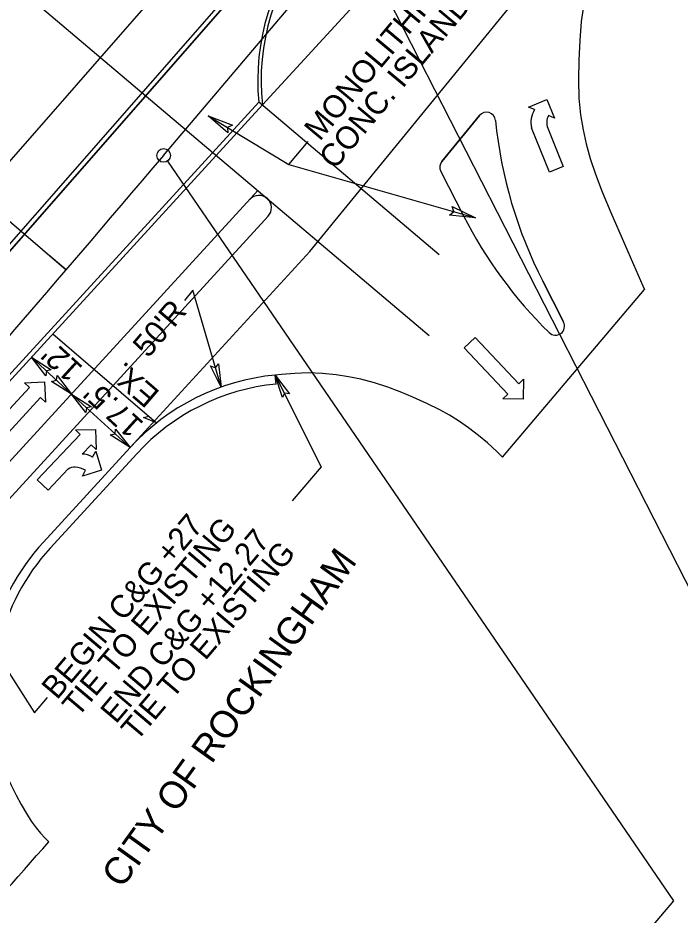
# Model space of a CAD drawing. Extents: x 1761082 to 1764358, y 421907 to 425434.
# Drawn here: x 1763028.7 to 1763174.6, y 423828.1 to 424026 of the extents above; entities that cross this region are included whole.
import ezdxf

# ---------------------------------------------------------------- set-up
doc = ezdxf.new("R2010")
doc.units = 0
for name, color, linetype in [('MARK DUAL LEFT TURN ARROWS CELL', 7, 'Continuous'), ('MARK HOOKS CENTER STRAIGHT LEFT TURN ARROW CELL', 7, 'Continuous'), ('MARK LEFT TURN ARROW CELL', 7, 'Continuous'), ('MARK STRAIGHT RIGHT ARROW CELL', 7, 'Continuous'), ('MARK UTURN ARROW CELL', 7, 'Continuous'), ('Prop Mkg 3ft Min Skp 3ft Wide White', 7, 'Continuous'), ('Prop Mkg Min Skp 6ft Yellow', 7, 'Continuous'), ('Prop Mkg Skp Wht', 7, 'Continuous'), ('Prop Mkg Solid White Diagonals', 7, 'Continuous'), ('Prop Mkg Solid White Lane Line', 7, 'Continuous'), ('Prop Mkg Solid White Multiple Diagonals V8i', 7, 'Continuous'), ('Prop Mkg Solid Yel Skip LT', 7, 'Continuous'), ('Prop Mkg Solid Yel Skip RT', 7, 'Continuous'), ('Prop Mkg Solid Yellow Diagonals', 7, 'Continuous'), ('Prop Mkg Solid Yellow Edge Line', 7, 'Continuous'), ('Prop Mkg Solid Yellow Lane Line', 7, 'Continuous'), ('Scratch_Level_0', 7, 'Continuous'), ('Scratch_Level_5', 7, 'Continuous')]:
    doc.layers.add(name, color=color, linetype=linetype)

msp = doc.modelspace()

# ---------------------------------------------------------------- linework, layer by layer
at = {"layer": 'MARK DUAL LEFT TURN ARROWS CELL'}
msp.add_line((1762975.13, 424025.41), (1763039.28, 423970.45), dxfattribs=at)
at = {"layer": 'MARK HOOKS CENTER STRAIGHT LEFT TURN ARROW CELL'}
msp.add_line((1763039.28, 423970.45), (1763035.48, 423973.71), dxfattribs=at)
at = {"layer": 'MARK LEFT TURN ARROW CELL'}
for p, q in [((1763085.59, 423945.25), (1763085.39, 423947.25)), ((1763035.74, 423909.03), (1763054.85, 423929.9))]:
    msp.add_line(p, q, dxfattribs=at)
for centre, start, end in [((1763090.25, 423897.48), 95.5758, 137.5234), ((1763071.14, 423876.61), 137.5234, 166.7543)]:
    msp.add_arc(centre, 48, start, end, dxfattribs=at)
at = {"layer": 'MARK STRAIGHT RIGHT ARROW CELL'}
msp.add_line((1763060.78, 423995.7), (1763460.21, 424467.19), dxfattribs=at)
msp.add_arc((1758482.74, 427874.03), 6000, 317.523415, 319.730103, dxfattribs=at)
at = {"layer": 'MARK UTURN ARROW CELL'}
msp.add_lwpolyline([(1763061.63, 423994.46), (1763173.2, 423831.29), (1763102.23, 423747.51)], dxfattribs=at)
msp.add_circle((1763060.78, 423995.7), 1.5, dxfattribs=at)
at = {"layer": 'Prop Mkg 3ft Min Skp 3ft Wide White'}
msp.add_line((1763060.78, 423995.7), (1763460.21, 424467.19), dxfattribs=at)
msp.add_arc((1758482.74, 427874.03), 6000, 317.523415, 319.730103, dxfattribs=at)
at = {"layer": 'Prop Mkg Skp Wht'}
for p, q in [((1763135.48, 423929.16), (1763166.78, 423966.11)), ((1763034.27, 423910.38), (1763053.37, 423931.25))]:
    msp.add_line(p, q, dxfattribs=at)
for points in [[(1763153.38, 424029.09), (1763152.86, 424025.26), (1763152.54, 424021.03), (1763152.32, 424016.7), (1763152.21, 424012.38), (1763152.34, 424008.35), (1763152.71, 424004.67), (1763153.24, 424001.33), (1763153.92, 423998.27), (1763154.83, 423995.03), (1763155.99, 423991.53), (1763157.46, 423987.67), (1763159.37, 423983.14), (1763162.39, 423976.16), (1763164.36, 423971.64), (1763166.43, 423966.9), (1763166.78, 423966.11)], [(1763135.48, 423929.16), (1763134.24, 423930.4), (1763132.21, 423932.26), (1763130.17, 423933.94), (1763127.97, 423935.61), (1763125.8, 423937.13), (1763123.83, 423938.39), (1763121.64, 423939.6), (1763118.78, 423940.99), (1763115.72, 423942.37), (1763112.95, 423943.56), (1763110.2, 423944.6), (1763107.23, 423945.54), (1763104.27, 423946.31), (1763101.54, 423946.87), (1763098.79, 423947.27), (1763095.77, 423947.56), (1763092.66, 423947.7), (1763089.68, 423947.61), (1763086.78, 423947.38), (1763085.39, 423947.25)], [(1763022.48, 423888.07), (1763022.37, 423887.64), (1763022.01, 423885.7), (1763021.78, 423883.92), (1763021.64, 423882.16), (1763021.52, 423880.28), (1763021.46, 423878.23), (1763021.51, 423875.93), (1763021.77, 423873.37), (1763022.32, 423870.5), (1763022.98, 423867.75), (1763023.58, 423865.5), (1763024.23, 423863.47), (1763025.04, 423861.39), (1763026, 423859.2), (1763027.08, 423856.89), (1763028.24, 423854.59), (1763029.39, 423852.48), (1763030.53, 423850.55), (1763031.6, 423848.83), (1763032.64, 423847.34), (1763033.63, 423846.15), (1763034.61, 423845.13), (1763035.49, 423844.29)]]:
    msp.add_lwpolyline(points, dxfattribs=at)
for centre, radius, start, end in [((1763090.25, 423897.48), 50, 95.5758, 137.5234), ((1763071.14, 423876.61), 50, 137.5234, 166.7543), ((1758482.74, 427874.03), 6080, 318.179172, 318.487231)]:
    msp.add_arc(centre, radius, start, end, dxfattribs=at)
at = {"layer": 'Prop Mkg Solid White Diagonals'}
for p, q in [((1763090.51, 424047.41), (1762859.56, 423783.42)), ((1762783.48, 423681.64), (1763081.76, 424007.42)), ((1763130.4, 424004.48), (1763122.12, 423994.36)), ((1763121.88, 423992.18), (1763126.88, 423982.39)), ((1763148.94, 423958.95), (1763144.36, 423967.93))]:
    msp.add_line(p, q, dxfattribs=at)
for centre, radius, start, end in [((1763131.52, 424012.29), 50, 139.7301, 185.5882), ((1763131.94, 424003.22), 2, 5.7105, 140.7423), ((1763233.44, 424013.37), 100, 185.7105, 207.0244), ((1763123.67, 423993.09), 2, 140.7423, 207.0244), ((1763215.96, 424027.83), 100, 207.0244, 225.4056), ((1763147.16, 423958.04), 2, 225.4056, 27.0244)]:
    msp.add_arc(centre, radius, start, end, dxfattribs=at)
at = {"layer": 'Prop Mkg Solid White Lane Line'}
for p, q in [((1762859.56, 423783.42), (1763090.51, 424047.41)), ((1762783.48, 423681.64), (1763081.76, 424007.42)), ((1763122.12, 423994.36), (1763130.4, 424004.48)), ((1763121.88, 423992.18), (1763126.88, 423982.39)), ((1763144.36, 423967.93), (1763148.94, 423958.95))]:
    msp.add_line(p, q, dxfattribs=at)
for centre, radius, start, end in [((1763131.52, 424012.29), 50, 139.7301, 185.5882), ((1763131.94, 424003.22), 2, 5.7105, 140.7423), ((1763233.44, 424013.37), 100, 185.7105, 207.0244), ((1763123.67, 423993.09), 2, 140.7423, 207.0244), ((1763215.96, 424027.83), 100, 207.0244, 225.4056), ((1763147.16, 423958.04), 2, 225.4056, 27.0244)]:
    msp.add_arc(centre, radius, start, end, dxfattribs=at)
at = {"layer": 'Prop Mkg Solid White Multiple Diagonals V8i'}
for p, q in [((1763006.96, 424051.12), (1763119.33, 423955.94)), ((1763102.71, 424045.18), (1763292.23, 423673.61)), ((1763121.49, 423973.76), (1763081.76, 424007.42)), ((1762988.96, 423878.66), (1763083.82, 423982.27))]:
    msp.add_line(p, q, dxfattribs=at)
msp.add_arc((1763081.79, 423984.13), 2.75, 317.5234, 137.5234, dxfattribs=at)
at = {"layer": 'Prop Mkg Solid Yel Skip RT'}
for p, q in [((1763088.35, 423993.73), (1763129.54, 423981.93)), ((1763040.47, 423943.06), (1763031.61, 423951.17)), ((1763053.37, 423931.25), (1763040.47, 423943.06))]:
    msp.add_line(p, q, dxfattribs=at)
for points in [[(1763070.57, 424004.41), (1763088.35, 423993.73), (1763092.61, 423998.75)], [(1763073.44, 423944.57), (1763067.25, 423965.96), (1763065.36, 423963.72)], [(1763085.39, 423947.25), (1763095.5, 423927.03), (1763089.11, 423919.49)], [(1763022.48, 423888.07), (1763032.31, 423872.76), (1763035.15, 423876.11)]]:
    msp.add_lwpolyline(points, dxfattribs=at)
at = {"layer": 'Prop Mkg Solid Yellow Diagonals'}
for p, q in [((1763141.2, 424006.38), (1763145.26, 424008.06)), ((1763145.26, 424008.06), (1763146.98, 424003.9)), ((1763142.56, 424005.8), (1763141.2, 424006.38)), ((1763146.98, 424003.9), (1763145.62, 424004.49)), ((1763145.81, 423992.02), (1763141.89, 424001.81)), ((1763145.48, 424001.74), (1763148.88, 423993.25)), ((1763148.88, 423993.25), (1763145.81, 423992.02)), ((1763127.07, 423953.26), (1763129.48, 423955.52)), ((1763129.48, 423955.52), (1763139.05, 423945.3)), ((1763136.64, 423943.04), (1763127.07, 423953.26)), ((1763030.07, 423945.53), (1763034.48, 423945.75)), ((1763031.17, 423944.51), (1763030.07, 423945.53)), ((1763034.48, 423945.75), (1763034.71, 423941.26)), ((1763139.05, 423945.3), (1763140.14, 423946.32)), ((1763140.14, 423946.32), (1763140.03, 423941.9)), ((1763021.7, 423934.21), (1763031.17, 423944.51)), ((1763033.6, 423942.28), (1763024.13, 423931.98)), ((1763034.71, 423941.26), (1763033.6, 423942.28)), ((1763135.54, 423942.02), (1763136.64, 423943.04)), ((1763140.03, 423941.9), (1763135.54, 423942.02)), ((1763032.91, 423924.11), (1763042.4, 423934.14)), ((1763041.31, 423935.17), (1763045.73, 423935.25)), ((1763042.4, 423934.14), (1763041.31, 423935.17)), ((1763045.73, 423935.25), (1763045.88, 423930.84)), ((1763044.79, 423931.87), (1763042.83, 423929.8)), ((1763045.88, 423930.84), (1763044.79, 423931.87)), ((1763045.12, 423929.15), (1763045.82, 423930.48)), ((1763045.82, 423930.48), (1763047.11, 423926.24)), ((1763039.74, 423926.53), (1763035.31, 423921.84)), ((1763047.11, 423926.24), (1763042.86, 423924.95)), ((1763042.86, 423924.95), (1763043.53, 423926.24)), ((1763035.31, 423921.84), (1763032.91, 423924.11))]:
    msp.add_line(p, q, dxfattribs=at)
for centre, radius, start, end in [((1763146.99, 424003), 5.25, 147.8228, 193.1345), ((1763148.5, 424002.96), 3.27, 152.1524, 201.8105), ((1763042.77, 423925.38), 4.43, 58.1749, 89.0535), ((1763041.08, 423924.38), 2.52, 85.6572, 121.9692), ((1763041.2, 423922.47), 4.43, 58.2937, 89.1473)]:
    msp.add_arc(centre, radius, start, end, dxfattribs=at)
at = {"layer": 'Prop Mkg Solid Yellow Edge Line'}
for p, q in [((1762898.9, 423848.13), (1763091.01, 424067.73)), ((1763082.58, 424006.83), (1763118.85, 424046.44)), ((1762975.24, 423871.83), (1763081.55, 423987.94))]:
    msp.add_line(p, q, dxfattribs=at)
at = {"layer": 'Prop Mkg Solid Yellow Lane Line'}
for points in [[(1763074.93, 424000.65), (1763070.57, 424004.41), (1763075.98, 424002.34), (1763074.84, 424001.85)], [(1763124.36, 423984.43), (1763129.54, 423981.93), (1763123.78, 423982.53), (1763124.76, 423983.3)], [(1763034.78, 423947.07), (1763031.61, 423951.17), (1763036.01, 423948.37), (1763034.92, 423948.14)], [(1763072.86, 423949.72), (1763073.44, 423944.57), (1763071.14, 423949.25), (1763072.19, 423948.87)], [(1763037.3, 423947.16), (1763040.47, 423943.06), (1763036.07, 423945.86), (1763037.16, 423946.09)], [(1763086.96, 423942.31), (1763085.39, 423947.25), (1763088.56, 423943.11), (1763087.45, 423943.27)], [(1763043.64, 423938.97), (1763040.47, 423943.06), (1763044.86, 423940.27), (1763043.77, 423940.04)], [(1763050.2, 423935.34), (1763053.37, 423931.25), (1763048.98, 423934.04), (1763050.07, 423934.27)]]:
    msp.add_lwpolyline(points, close=True, dxfattribs=at)
at = {"layer": 'Scratch_Level_0'}
for p, q in [((1763092.98, 423974.51), (1763191.95, 424095.61)), ((1762858.8, 423784.07), (1763100.11, 424059.9)), ((1762790.28, 423687.58), (1763082.58, 424006.83)), ((1763053.37, 423931.25), (1763092.98, 423974.51))]:
    msp.add_line(p, q, dxfattribs=at)
msp.add_arc((1763131.52, 424012.29), 49.25, 139.7301, 186.3635, dxfattribs=at)
at = {"layer": 'Scratch_Level_5'}
msp.add_line((1763036.37, 423956.36), (1763059.23, 423936.7), dxfattribs=at)
msp.add_lwpolyline([(1763059.23, 423936.7), (1763056.31, 423937.9), (1763057.48, 423938.21)], close=True, dxfattribs=at)

# ---------------------------------------------------------------- texts
at = {"layer": 'Prop Mkg Min Skp 6ft Yellow'}
msp.add_text('EX.', height=5, rotation=139.2933, dxfattribs=at).set_placement((1763060.18, 423943.46))
at = {"layer": 'Prop Mkg Solid Yel Skip LT'}
for s, height, rotation, p in [('MONOLITHIC', 5, 50.1302, (1763095.2, 423998.67)), ('CONC. ISLAND', 5, 50.1302, (1763098.47, 423992.36)), ("50'R", 5, 49.7301, (1763057.38, 423950.82)), ("12'", 5, 137.5234, (1763043.22, 423948.94)), ("17.5'", 5, 137.5234, (1763056.64, 423936.63)), ('BEGIN C&G +27', 5, 49.7301, (1763037.27, 423875.43)), ('TIE TO EXISTING', 5, 49.7301, (1763041.85, 423871.55)), ('END C&G +12.27', 5, 49.7301, (1763050.25, 423870.12)), ('TIE TO EXISTING', 5, 49.7301, (1763054.83, 423866.24)), ('CITY OF ROCKINGHAM', 6, 54.291, (1763051.57, 423833.75))]:
    msp.add_text(s, height=height, rotation=rotation, dxfattribs=at).set_placement(p)

doc.saveas('drawing.dxf')
